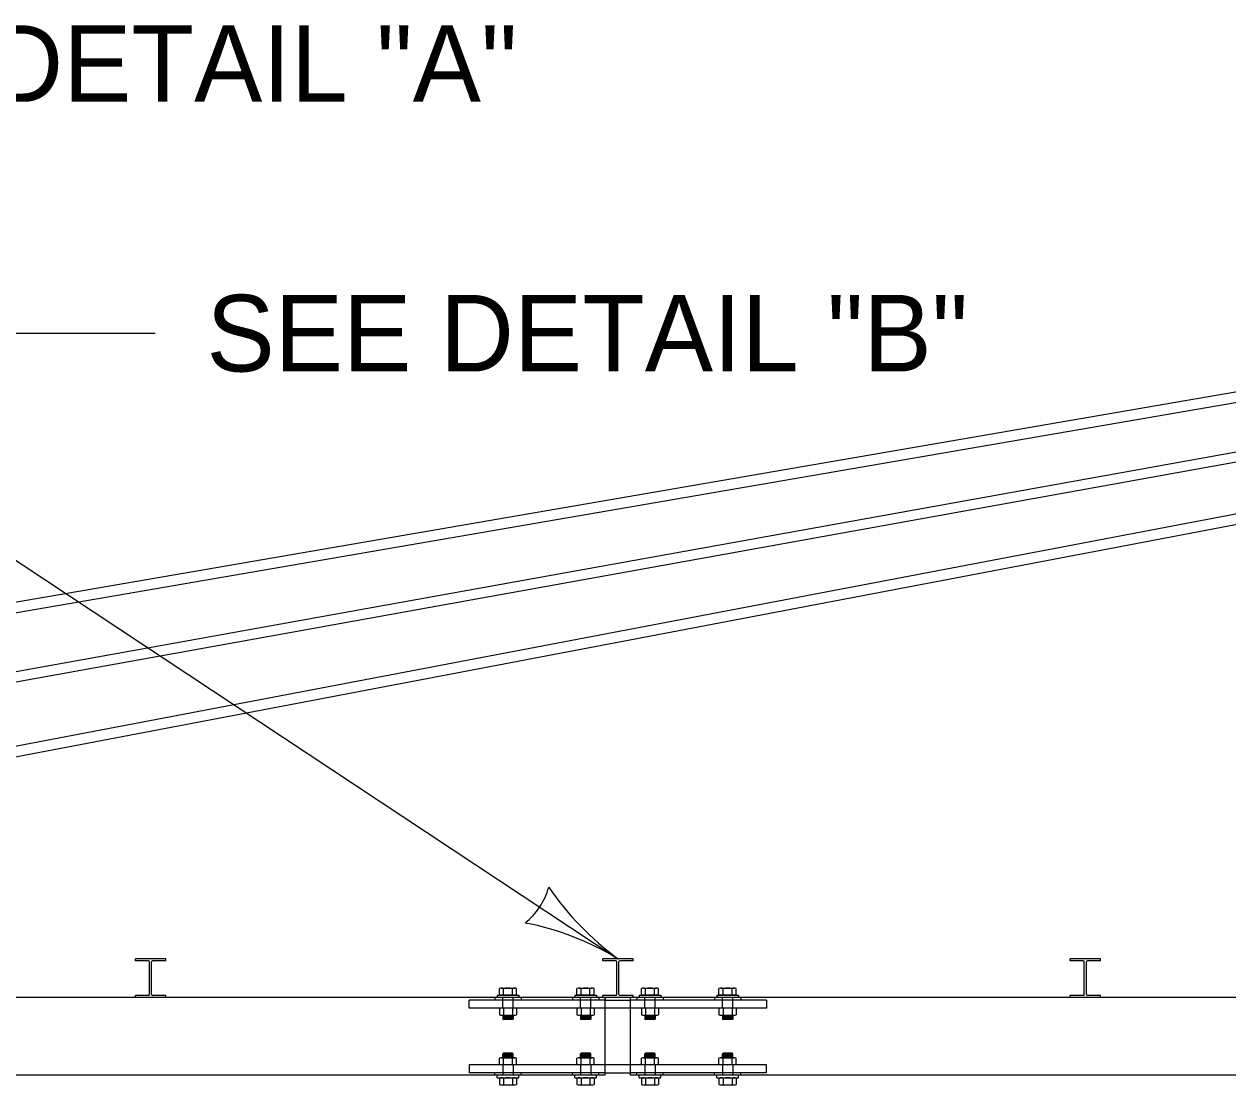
# Model space of a CAD drawing. Extents: x 49991.4 to 50021, y 49987.6 to 50011.4.
# Drawn here: x 50004.377 to 50005.32, y 49996.741 to 49997.572 of the extents above; entities that cross this region are included whole.
import ezdxf

# ---------------------------------------------------------------- set-up
doc = ezdxf.new("R2010")
doc.units = 0
for name, color, linetype in [('Level 1', 7, 'Continuous'), ('Level 2', 7, 'Continuous'), ('Level 3', 7, 'Continuous'), ('Level 4', 7, 'Continuous')]:
    doc.layers.add(name, color=color, linetype=linetype)

msp = doc.modelspace()

# ---------------------------------------------------------------- linework, layer by layer
at = {"layer": 'Level 1'}
for p, q in [((50002.8842, 49996.86275), (50006.12112, 49997.4208)), ((50002.88578, 49996.85474), (50006.12265, 49997.41281)), ((50003.25008, 49996.86273), (50006.12834, 49997.38128)), ((50003.25178, 49996.85474), (50006.1298, 49997.37361)), ((50003.6162, 49996.86274), (50006.13548, 49997.34215)), ((50003.61778, 49996.85474), (50006.137, 49997.33416)), ((50004.48824, 49996.83972), (50004.46456, 49996.83972)), ((50004.46456, 49996.83812), (50004.46456, 49996.83972)), ((50004.4748, 49996.83812), (50004.46456, 49996.83812)), ((50004.4756, 49996.81164), (50004.4756, 49996.83732)), ((50004.4772, 49996.81164), (50004.4772, 49996.83732)), ((50004.48824, 49996.83812), (50004.478, 49996.83812)), ((50004.48824, 49996.83812), (50004.48824, 49996.83972)), ((50004.85424, 49996.83972), (50004.83056, 49996.83972)), ((50004.83056, 49996.83812), (50004.83056, 49996.83972)), ((50004.8408, 49996.83812), (50004.83056, 49996.83812)), ((50004.8416, 49996.81164), (50004.8416, 49996.83732)), ((50004.8432, 49996.81164), (50004.8432, 49996.83732)), ((50004.85424, 49996.83812), (50004.844, 49996.83812)), ((50004.85424, 49996.83812), (50004.85424, 49996.83972)), ((50005.22024, 49996.83972), (50005.19656, 49996.83972)), ((50005.19656, 49996.83812), (50005.19656, 49996.83972)), ((50005.2068, 49996.83812), (50005.19656, 49996.83812)), ((50005.2076, 49996.81164), (50005.2076, 49996.83732)), ((50005.2092, 49996.81164), (50005.2092, 49996.83732)), ((50005.22024, 49996.83812), (50005.21, 49996.83812)), ((50005.22024, 49996.83812), (50005.22024, 49996.83972)), ((50004.74951, 49996.81157), (50004.74951, 49996.81646)), ((50004.7512, 49996.81674), (50004.76134, 49996.81674)), ((50004.75286, 49996.81156), (50004.75286, 49996.81647)), ((50004.7597, 49996.81156), (50004.7597, 49996.81644)), ((50004.76305, 49996.81157), (50004.76305, 49996.81646)), ((50004.81031, 49996.81157), (50004.81031, 49996.81646)), ((50004.812, 49996.81674), (50004.82214, 49996.81674)), ((50004.81366, 49996.81156), (50004.81366, 49996.81647)), ((50004.8205, 49996.81156), (50004.8205, 49996.81644)), ((50004.82385, 49996.81157), (50004.82385, 49996.81646)), ((50004.86071, 49996.81157), (50004.86071, 49996.81646)), ((50004.8624, 49996.81674), (50004.87254, 49996.81674)), ((50004.86406, 49996.81156), (50004.86406, 49996.81647)), ((50004.8709, 49996.81156), (50004.8709, 49996.81644)), ((50004.87425, 49996.81157), (50004.87425, 49996.81646)), ((50004.92151, 49996.81157), (50004.92151, 49996.81646)), ((50004.9232, 49996.81674), (50004.93334, 49996.81674)), ((50004.92486, 49996.81156), (50004.92486, 49996.81647)), ((50004.9317, 49996.81156), (50004.9317, 49996.81646)), ((50004.93505, 49996.81157), (50004.93505, 49996.81646)), ((50004.83228, 49996.80924), (50002.6464, 49996.80924)), ((50004.46456, 49996.80924), (50004.46456, 49996.81084)), ((50004.4748, 49996.81084), (50004.46456, 49996.81084)), ((50004.48824, 49996.81084), (50004.478, 49996.81084)), ((50004.48824, 49996.80924), (50004.48824, 49996.81084)), ((50004.7479, 49996.81124), (50004.76467, 49996.81124)), ((50004.7479, 49996.81124), (50004.7479, 49996.80924)), ((50004.7512, 49996.81129), (50004.76134, 49996.81129)), ((50004.76467, 49996.81124), (50004.76467, 49996.80924)), ((50004.8087, 49996.81124), (50004.82547, 49996.81124)), ((50004.8087, 49996.81124), (50004.8087, 49996.80924)), ((50004.812, 49996.81129), (50004.82214, 49996.81129)), ((50004.82547, 49996.81124), (50004.82547, 49996.80924)), ((50004.83056, 49996.80924), (50004.83056, 49996.81084)), ((50004.8408, 49996.81084), (50004.83056, 49996.81084)), ((50004.85424, 49996.80924), (50004.83056, 49996.80924)), ((50004.83228, 49996.74844), (50004.83228, 49996.80924)), ((50004.83228, 49996.80924), (50004.83228, 49996.80732)), ((50004.83228, 49996.80732), (50004.85228, 49996.80732)), ((50004.85424, 49996.81084), (50004.844, 49996.81084)), ((50004.85228, 49996.74844), (50004.85228, 49996.80924)), ((50007.0284, 49996.80924), (50004.85228, 49996.80924)), ((50004.85424, 49996.80924), (50004.85424, 49996.81084)), ((50004.8591, 49996.81124), (50004.87587, 49996.81124)), ((50004.8591, 49996.81124), (50004.8591, 49996.80924)), ((50004.8624, 49996.81129), (50004.87254, 49996.81129)), ((50004.87587, 49996.81124), (50004.87587, 49996.80924)), ((50004.9199, 49996.81124), (50004.93667, 49996.81124)), ((50004.9199, 49996.81124), (50004.9199, 49996.80924)), ((50004.9232, 49996.81129), (50004.93334, 49996.81129)), ((50004.93667, 49996.81124), (50004.93667, 49996.80924)), ((50005.19656, 49996.80924), (50005.19656, 49996.81084)), ((50005.2068, 49996.81084), (50005.19656, 49996.81084)), ((50005.22024, 49996.81084), (50005.21, 49996.81084)), ((50005.22024, 49996.80924), (50005.22024, 49996.81084)), ((50004.85228, 49996.80096), (50004.83228, 49996.80096)), ((50004.85228, 49996.75672), (50004.83228, 49996.75672)), ((50004.83228, 49996.74844), (50004.83228, 49996.75036)), ((50004.83228, 49996.75036), (50004.85228, 49996.75036)), ((50004.83228, 49996.74844), (50004.1916, 49996.74844)), ((50004.7479, 49996.74645), (50004.7479, 49996.74844)), ((50004.7479, 49996.74645), (50004.76467, 49996.74645)), ((50004.74951, 49996.74612), (50004.74951, 49996.74123)), ((50004.7512, 49996.7464), (50004.76134, 49996.7464)), ((50004.7512, 49996.74095), (50004.76134, 49996.74095)), ((50004.75286, 49996.74613), (50004.75286, 49996.74122)), ((50004.7597, 49996.74613), (50004.7597, 49996.74124)), ((50004.76305, 49996.74612), (50004.76305, 49996.74123)), ((50004.76467, 49996.74645), (50004.76467, 49996.74844)), ((50004.8087, 49996.74645), (50004.8087, 49996.74844)), ((50004.8087, 49996.74645), (50004.82547, 49996.74645)), ((50004.81031, 49996.74612), (50004.81031, 49996.74123)), ((50004.812, 49996.7464), (50004.82214, 49996.7464)), ((50004.812, 49996.74095), (50004.82214, 49996.74095)), ((50004.81366, 49996.74613), (50004.81366, 49996.74122)), ((50004.8205, 49996.74613), (50004.8205, 49996.74124)), ((50004.82385, 49996.74612), (50004.82385, 49996.74123)), ((50004.82547, 49996.74645), (50004.82547, 49996.74844)), ((50007.0284, 49996.74844), (50004.85228, 49996.74844)), ((50004.8591, 49996.74645), (50004.8591, 49996.74844)), ((50004.8591, 49996.74645), (50004.87587, 49996.74645)), ((50004.86071, 49996.74612), (50004.86071, 49996.74123)), ((50004.8624, 49996.7464), (50004.87254, 49996.7464)), ((50004.8624, 49996.74095), (50004.87254, 49996.74095)), ((50004.86406, 49996.74613), (50004.86406, 49996.74122)), ((50004.8709, 49996.74613), (50004.8709, 49996.74124)), ((50004.87425, 49996.74612), (50004.87425, 49996.74123)), ((50004.87587, 49996.74645), (50004.87587, 49996.74844)), ((50004.9199, 49996.74645), (50004.9199, 49996.74844)), ((50004.9199, 49996.74645), (50004.93667, 49996.74645)), ((50004.92151, 49996.74612), (50004.92151, 49996.74123)), ((50004.9232, 49996.7464), (50004.93334, 49996.7464)), ((50004.9232, 49996.74095), (50004.93334, 49996.74095)), ((50004.92486, 49996.74613), (50004.92486, 49996.74122)), ((50004.9317, 49996.74613), (50004.9317, 49996.74124)), ((50004.93505, 49996.74612), (50004.93505, 49996.74123)), ((50004.93667, 49996.74645), (50004.93667, 49996.74844))]:
    msp.add_line(p, q, dxfattribs=at)
for centre, start, end in [((50004.4748, 49996.83732), 0, 90), ((50004.478, 49996.83732), 90, 180), ((50004.8408, 49996.83732), 0, 90), ((50004.844, 49996.83732), 90, 180), ((50005.2068, 49996.83732), 0, 90), ((50005.21, 49996.83732), 90, 180), ((50004.4748, 49996.81164), 270, 0), ((50004.478, 49996.81164), 180, 270), ((50004.8408, 49996.81164), 270, 0), ((50004.844, 49996.81164), 180, 270), ((50005.2068, 49996.81164), 270, 0), ((50005.21, 49996.81164), 180, 270)]:
    msp.add_arc(centre, 0.0008, start, end, dxfattribs=at)
for centre, major_axis, start_param, end_param in [((50004.7512, 49996.81463), (0.00339, 0), 1.056847, 2.094396), ((50004.75628, 49996.80829), (0.01355, 0), 1.315951, 1.825641), ((50004.76136, 49996.81463), (0.00339, 0), 1.047198, 2.084746), ((50004.812, 49996.81463), (0.00339, 0), 1.056847, 2.094396), ((50004.81708, 49996.80829), (0.01355, 0), 1.315951, 1.825641), ((50004.82216, 49996.81463), (0.00339, 0), 1.047198, 2.084746), ((50004.8624, 49996.81463), (0.00339, 0), 1.056847, 2.094396), ((50004.86748, 49996.80829), (0.01355, 0), 1.315951, 1.825641), ((50004.87256, 49996.81463), (0.00339, 0), 1.047198, 2.084746), ((50004.9232, 49996.81463), (0.00339, 0), 1.056847, 2.094396), ((50004.92828, 49996.80829), (0.01355, 0), 1.315951, 1.825641), ((50004.93336, 49996.81463), (0.00339, 0), 1.047198, 2.084746), ((50004.7512, 49996.8134), (0.00339, 0), 4.188789, 5.226338), ((50004.75628, 49996.81974), (0.01355, 0), 4.457545, 4.967235), ((50004.76136, 49996.8134), (0.00339, 0), 4.198439, 5.235988), ((50004.812, 49996.8134), (0.00339, 0), 4.188789, 5.226338), ((50004.81708, 49996.81974), (0.01355, 0), 4.457545, 4.967235), ((50004.82216, 49996.8134), (0.00339, 0), 4.198439, 5.235988), ((50004.8624, 49996.8134), (0.00339, 0), 4.188789, 5.226338), ((50004.86748, 49996.81974), (0.01355, 0), 4.457545, 4.967235), ((50004.87256, 49996.8134), (0.00339, 0), 4.198439, 5.235988), ((50004.9232, 49996.8134), (0.00339, 0), 4.188789, 5.226338), ((50004.92828, 49996.81974), (0.01355, 0), 4.457545, 4.967235), ((50004.93336, 49996.8134), (0.00339, 0), 4.198439, 5.235988), ((50004.7512, 49996.74429), (0.00339, 0), 1.056847, 2.094396), ((50004.7512, 49996.74306), (0.00339, 0), 4.188789, 5.226338), ((50004.75628, 49996.73795), (0.01355, 0), 1.31595, 1.825641), ((50004.75628, 49996.7494), (0.01355, 0), 4.457545, 4.967234), ((50004.76136, 49996.74429), (0.00339, 0), 1.047198, 2.084746), ((50004.76136, 49996.74306), (0.00339, 0), 4.198439, 5.235988), ((50004.812, 49996.74429), (0.00339, 0), 1.056847, 2.094396), ((50004.812, 49996.74306), (0.00339, 0), 4.188789, 5.226338), ((50004.81708, 49996.73795), (0.01355, 0), 1.31595, 1.825641), ((50004.81708, 49996.7494), (0.01355, 0), 4.457545, 4.967234), ((50004.82216, 49996.74429), (0.00339, 0), 1.047198, 2.084746), ((50004.82216, 49996.74306), (0.00339, 0), 4.198439, 5.235988), ((50004.8624, 49996.74429), (0.00339, 0), 1.056847, 2.094396), ((50004.8624, 49996.74306), (0.00339, 0), 4.188789, 5.226338), ((50004.86748, 49996.73795), (0.01355, 0), 1.31595, 1.825641), ((50004.86748, 49996.7494), (0.01355, 0), 4.457545, 4.967234), ((50004.87256, 49996.74429), (0.00339, 0), 1.047198, 2.084746), ((50004.87256, 49996.74306), (0.00339, 0), 4.198439, 5.235988), ((50004.9232, 49996.74429), (0.00339, 0), 1.056847, 2.094396), ((50004.9232, 49996.74306), (0.00339, 0), 4.188789, 5.226338), ((50004.92828, 49996.73795), (0.01355, 0), 1.31595, 1.825641), ((50004.92828, 49996.7494), (0.01355, 0), 4.457545, 4.967234), ((50004.93336, 49996.74429), (0.00339, 0), 1.047198, 2.084746), ((50004.93336, 49996.74306), (0.00339, 0), 4.198439, 5.235988)]:
    msp.add_ellipse(centre, major_axis=major_axis, ratio=0.623816, start_param=start_param, end_param=end_param, dxfattribs=at)
at = {"layer": 'Level 3'}
for p, q in [((50004.34941, 49997.32964), (50004.48011, 49997.32964)), ((50004.31385, 49997.18926), (50004.8424, 49996.83972))]:
    msp.add_line(p, q, dxfattribs=at)
for centre, radius, start, end in [((50004.73546, 49996.91044), 0.05477, 308.66104, 344.3834), ((50004.98035, 49997.02748), 0.233, 214.44506, 233.69491), ((50004.72751, 49996.64939), 0.22232, 58.8827, 79.06621)]:
    msp.add_arc(centre, radius, start, end, dxfattribs=at)
at = {"layer": 'Level 4'}
for p, q in [((50004.72588, 49996.80096), (50004.72588, 49996.80732)), ((50004.83228, 49996.80732), (50004.72588, 49996.80732)), ((50004.7459, 49996.80924), (50004.7459, 49996.80732)), ((50004.75228, 49996.80096), (50004.75228, 49996.80924)), ((50004.76028, 49996.80096), (50004.76028, 49996.80924)), ((50004.76667, 49996.80924), (50004.76667, 49996.80732)), ((50004.8067, 49996.80924), (50004.8067, 49996.80732)), ((50004.81309, 49996.80096), (50004.81309, 49996.80924)), ((50004.82109, 49996.80096), (50004.82109, 49996.80924)), ((50004.82747, 49996.80924), (50004.82747, 49996.80732)), ((50004.95868, 49996.80732), (50004.85228, 49996.80732)), ((50004.8571, 49996.80924), (50004.8571, 49996.80732)), ((50004.86348, 49996.80096), (50004.86348, 49996.80924)), ((50004.87148, 49996.80096), (50004.87148, 49996.80924)), ((50004.87787, 49996.80924), (50004.87787, 49996.80732)), ((50004.9179, 49996.80924), (50004.9179, 49996.80732)), ((50004.92429, 49996.80096), (50004.92429, 49996.80924)), ((50004.93229, 49996.80096), (50004.93229, 49996.80924)), ((50004.93867, 49996.80924), (50004.93867, 49996.80732)), ((50004.95868, 49996.80732), (50004.95868, 49996.80096)), ((50004.83228, 49996.80096), (50004.72588, 49996.80096)), ((50004.74951, 49996.80068), (50004.74951, 49996.79579)), ((50004.75286, 49996.80069), (50004.75286, 49996.79579)), ((50004.75971, 49996.80069), (50004.75971, 49996.79578)), ((50004.76306, 49996.80068), (50004.76306, 49996.79579)), ((50004.81031, 49996.80068), (50004.81031, 49996.79579)), ((50004.81366, 49996.80069), (50004.81366, 49996.79579)), ((50004.82051, 49996.80069), (50004.82051, 49996.79578)), ((50004.82386, 49996.80068), (50004.82386, 49996.79579)), ((50004.95868, 49996.80096), (50004.85228, 49996.80096)), ((50004.86071, 49996.80068), (50004.86071, 49996.79579)), ((50004.86406, 49996.80069), (50004.86406, 49996.79579)), ((50004.87091, 49996.80069), (50004.87091, 49996.79578)), ((50004.87426, 49996.80068), (50004.87426, 49996.79579)), ((50004.92151, 49996.80068), (50004.92151, 49996.79579)), ((50004.92486, 49996.80069), (50004.92486, 49996.79578)), ((50004.93171, 49996.80069), (50004.93171, 49996.79578)), ((50004.93506, 49996.80068), (50004.93506, 49996.79579)), ((50004.75121, 49996.79551), (50004.76135, 49996.79551)), ((50004.75228, 49996.79551), (50004.75228, 49996.79244)), ((50004.75228, 49996.79244), (50004.75268, 49996.79204)), ((50004.75988, 49996.79524), (50004.75268, 49996.79524)), ((50004.75988, 49996.79444), (50004.75268, 49996.79444)), ((50004.75988, 49996.79364), (50004.75268, 49996.79364)), ((50004.75988, 49996.79284), (50004.75268, 49996.79284)), ((50004.75988, 49996.79204), (50004.75268, 49996.79204)), ((50004.76028, 49996.79244), (50004.75988, 49996.79204)), ((50004.76028, 49996.79551), (50004.76028, 49996.79244)), ((50004.81201, 49996.79551), (50004.82215, 49996.79551)), ((50004.81309, 49996.79551), (50004.81309, 49996.79244)), ((50004.81309, 49996.79244), (50004.81349, 49996.79204)), ((50004.82069, 49996.79524), (50004.81349, 49996.79524)), ((50004.82069, 49996.79444), (50004.81349, 49996.79444)), ((50004.82069, 49996.79364), (50004.81349, 49996.79364)), ((50004.82069, 49996.79284), (50004.81349, 49996.79284)), ((50004.82069, 49996.79204), (50004.81349, 49996.79204)), ((50004.82109, 49996.79244), (50004.82069, 49996.79204)), ((50004.82109, 49996.79551), (50004.82109, 49996.79244)), ((50004.86241, 49996.79551), (50004.87255, 49996.79551)), ((50004.86349, 49996.79551), (50004.86349, 49996.79244)), ((50004.86349, 49996.79244), (50004.86389, 49996.79204)), ((50004.87109, 49996.79524), (50004.86389, 49996.79524)), ((50004.87109, 49996.79444), (50004.86389, 49996.79444)), ((50004.87109, 49996.79364), (50004.86389, 49996.79364)), ((50004.87109, 49996.79284), (50004.86389, 49996.79284)), ((50004.87109, 49996.79204), (50004.86389, 49996.79204)), ((50004.87149, 49996.79244), (50004.87109, 49996.79204)), ((50004.87149, 49996.79551), (50004.87149, 49996.79244)), ((50004.92321, 49996.79551), (50004.93335, 49996.79551)), ((50004.92429, 49996.79551), (50004.92429, 49996.79244)), ((50004.92429, 49996.79244), (50004.92469, 49996.79204)), ((50004.93189, 49996.79524), (50004.92469, 49996.79524)), ((50004.93189, 49996.79444), (50004.92469, 49996.79444)), ((50004.93189, 49996.79364), (50004.92469, 49996.79364)), ((50004.93189, 49996.79284), (50004.92469, 49996.79284)), ((50004.93189, 49996.79204), (50004.92469, 49996.79204)), ((50004.93229, 49996.79244), (50004.93189, 49996.79204)), ((50004.93229, 49996.79551), (50004.93229, 49996.79244)), ((50004.74951, 49996.75701), (50004.74951, 49996.76189)), ((50004.75121, 49996.76218), (50004.76135, 49996.76218)), ((50004.75228, 49996.76525), (50004.75268, 49996.76565)), ((50004.75228, 49996.76218), (50004.75228, 49996.76525)), ((50004.75988, 49996.76565), (50004.75268, 49996.76565)), ((50004.75988, 49996.76485), (50004.75268, 49996.76485)), ((50004.75988, 49996.76405), (50004.75268, 49996.76405)), ((50004.75988, 49996.76325), (50004.75268, 49996.76325)), ((50004.75988, 49996.76245), (50004.75268, 49996.76245)), ((50004.75286, 49996.757), (50004.75286, 49996.7619)), ((50004.75971, 49996.757), (50004.75971, 49996.7619)), ((50004.76028, 49996.76525), (50004.75988, 49996.76565)), ((50004.76028, 49996.76218), (50004.76028, 49996.76525)), ((50004.76306, 49996.75701), (50004.76306, 49996.76189)), ((50004.81031, 49996.75701), (50004.81031, 49996.76189)), ((50004.81201, 49996.76218), (50004.82215, 49996.76218)), ((50004.81309, 49996.76525), (50004.81349, 49996.76565)), ((50004.81309, 49996.76218), (50004.81309, 49996.76525)), ((50004.82069, 49996.76565), (50004.81349, 49996.76565)), ((50004.82069, 49996.76485), (50004.81349, 49996.76485)), ((50004.82069, 49996.76405), (50004.81349, 49996.76405)), ((50004.82069, 49996.76325), (50004.81349, 49996.76325)), ((50004.82069, 49996.76245), (50004.81349, 49996.76245)), ((50004.81366, 49996.757), (50004.81366, 49996.7619)), ((50004.82051, 49996.757), (50004.82051, 49996.7619)), ((50004.82109, 49996.76525), (50004.82069, 49996.76565)), ((50004.82109, 49996.76218), (50004.82109, 49996.76525)), ((50004.82386, 49996.75701), (50004.82386, 49996.76189)), ((50004.86071, 49996.75701), (50004.86071, 49996.76189)), ((50004.86241, 49996.76218), (50004.87255, 49996.76218)), ((50004.86349, 49996.76525), (50004.86389, 49996.76565)), ((50004.86349, 49996.76218), (50004.86349, 49996.76525)), ((50004.87109, 49996.76565), (50004.86389, 49996.76565)), ((50004.87109, 49996.76485), (50004.86389, 49996.76485)), ((50004.87109, 49996.76405), (50004.86389, 49996.76405)), ((50004.87109, 49996.76325), (50004.86389, 49996.76325)), ((50004.87109, 49996.76245), (50004.86389, 49996.76245)), ((50004.86406, 49996.757), (50004.86406, 49996.7619)), ((50004.87091, 49996.757), (50004.87091, 49996.7619)), ((50004.87149, 49996.76525), (50004.87109, 49996.76565)), ((50004.87149, 49996.76218), (50004.87149, 49996.76525)), ((50004.87426, 49996.75701), (50004.87426, 49996.76189)), ((50004.92151, 49996.75701), (50004.92151, 49996.76189)), ((50004.92321, 49996.76218), (50004.93335, 49996.76218)), ((50004.92429, 49996.76525), (50004.92469, 49996.76565)), ((50004.92429, 49996.76218), (50004.92429, 49996.76525)), ((50004.93189, 49996.76565), (50004.92469, 49996.76565)), ((50004.93189, 49996.76485), (50004.92469, 49996.76485)), ((50004.93189, 49996.76405), (50004.92469, 49996.76405)), ((50004.93189, 49996.76325), (50004.92469, 49996.76325)), ((50004.93189, 49996.76245), (50004.92469, 49996.76245)), ((50004.92486, 49996.757), (50004.92486, 49996.7619)), ((50004.93171, 49996.757), (50004.93171, 49996.7619)), ((50004.93229, 49996.76525), (50004.93189, 49996.76565)), ((50004.93229, 49996.76218), (50004.93229, 49996.76525)), ((50004.93506, 49996.75701), (50004.93506, 49996.76189)), ((50004.72588, 49996.75672), (50004.72588, 49996.75036)), ((50004.83228, 49996.75672), (50004.72588, 49996.75672)), ((50004.83228, 49996.75036), (50004.72588, 49996.75036)), ((50004.7459, 49996.74844), (50004.7459, 49996.75036)), ((50004.75228, 49996.75672), (50004.75228, 49996.74844)), ((50004.76028, 49996.75672), (50004.76028, 49996.74844)), ((50004.76667, 49996.74844), (50004.76667, 49996.75036)), ((50004.8067, 49996.74844), (50004.8067, 49996.75036)), ((50004.81309, 49996.75672), (50004.81309, 49996.74844)), ((50004.82109, 49996.75672), (50004.82109, 49996.74844)), ((50004.82747, 49996.74844), (50004.82747, 49996.75036)), ((50004.95868, 49996.75672), (50004.85228, 49996.75672)), ((50004.95868, 49996.75036), (50004.85228, 49996.75036)), ((50004.8571, 49996.74844), (50004.8571, 49996.75036)), ((50004.86348, 49996.75672), (50004.86348, 49996.74844)), ((50004.87148, 49996.75672), (50004.87148, 49996.74844)), ((50004.87787, 49996.74844), (50004.87787, 49996.75036)), ((50004.9179, 49996.74844), (50004.9179, 49996.75036)), ((50004.92429, 49996.75672), (50004.92429, 49996.74844)), ((50004.93229, 49996.75672), (50004.93229, 49996.74844)), ((50004.93867, 49996.74844), (50004.93867, 49996.75036)), ((50004.95868, 49996.75036), (50004.95868, 49996.75672))]:
    msp.add_line(p, q, dxfattribs=at)
for centre, major_axis, start_param, end_param in [((50004.75121, 49996.79885), (0.00339, 0), 1.056847, 2.094396), ((50004.75629, 49996.79251), (0.01355, 0), 1.31595, 1.825641), ((50004.76137, 49996.79885), (0.00339, 0), 1.047198, 2.084746), ((50004.81201, 49996.79885), (0.00339, 0), 1.056847, 2.094396), ((50004.81709, 49996.79251), (0.01355, 0), 1.31595, 1.825641), ((50004.82217, 49996.79885), (0.00339, 0), 1.047198, 2.084746), ((50004.86241, 49996.79885), (0.00339, 0), 1.056847, 2.094396), ((50004.86749, 49996.79251), (0.01355, 0), 1.31595, 1.825641), ((50004.87257, 49996.79885), (0.00339, 0), 1.047198, 2.084746), ((50004.92321, 49996.79885), (0.00339, 0), 1.056847, 2.094396), ((50004.92829, 49996.79251), (0.01355, 0), 1.31595, 1.825641), ((50004.93337, 49996.79885), (0.00339, 0), 1.047198, 2.084746), ((50004.75121, 49996.79762), (0.00339, 0), 4.188789, 5.226338), ((50004.75629, 49996.80396), (0.01355, 0), 4.457545, 4.967234), ((50004.76137, 49996.79762), (0.00339, 0), 4.198439, 5.235988), ((50004.81201, 49996.79762), (0.00339, 0), 4.188789, 5.226338), ((50004.81709, 49996.80396), (0.01355, 0), 4.457545, 4.967234), ((50004.82217, 49996.79762), (0.00339, 0), 4.198439, 5.235988), ((50004.86241, 49996.79762), (0.00339, 0), 4.188789, 5.226338), ((50004.86749, 49996.80396), (0.01355, 0), 4.457545, 4.967234), ((50004.87257, 49996.79762), (0.00339, 0), 4.198439, 5.235988), ((50004.92321, 49996.79762), (0.00339, 0), 4.188789, 5.226338), ((50004.92829, 49996.80396), (0.01355, 0), 4.457545, 4.967234), ((50004.93337, 49996.79762), (0.00339, 0), 4.198439, 5.235988), ((50004.75121, 49996.76006), (0.00339, 0), 1.056847, 2.094396), ((50004.75629, 49996.75373), (0.01355, 0), 1.315951, 1.825641), ((50004.76137, 49996.76006), (0.00339, 0), 1.047198, 2.084746), ((50004.81201, 49996.76006), (0.00339, 0), 1.056847, 2.094396), ((50004.81709, 49996.75373), (0.01355, 0), 1.315951, 1.825641), ((50004.82217, 49996.76006), (0.00339, 0), 1.047198, 2.084746), ((50004.86241, 49996.76006), (0.00339, 0), 1.056847, 2.094396), ((50004.86749, 49996.75373), (0.01355, 0), 1.315951, 1.825641), ((50004.87257, 49996.76006), (0.00339, 0), 1.047198, 2.084746), ((50004.92321, 49996.76006), (0.00339, 0), 1.056847, 2.094396), ((50004.92829, 49996.75373), (0.01355, 0), 1.315951, 1.825641), ((50004.93337, 49996.76006), (0.00339, 0), 1.047198, 2.084746), ((50004.75121, 49996.75884), (0.00339, 0), 4.188789, 5.226338), ((50004.75629, 49996.76517), (0.01355, 0), 4.457545, 4.967235), ((50004.76137, 49996.75884), (0.00339, 0), 4.198439, 5.235988), ((50004.81201, 49996.75884), (0.00339, 0), 4.188789, 5.226338), ((50004.81709, 49996.76517), (0.01355, 0), 4.457545, 4.967235), ((50004.82217, 49996.75884), (0.00339, 0), 4.198439, 5.235988), ((50004.86241, 49996.75884), (0.00339, 0), 4.188789, 5.226338), ((50004.86749, 49996.76517), (0.01355, 0), 4.457545, 4.967235), ((50004.87257, 49996.75884), (0.00339, 0), 4.198439, 5.235988), ((50004.92321, 49996.75884), (0.00339, 0), 4.188789, 5.226338), ((50004.92829, 49996.76517), (0.01355, 0), 4.457545, 4.967235), ((50004.93337, 49996.75884), (0.00339, 0), 4.198439, 5.235988)]:
    msp.add_ellipse(centre, major_axis=major_axis, ratio=0.623816, start_param=start_param, end_param=end_param, dxfattribs=at)

# ---------------------------------------------------------------- texts
at = {"layer": 'Level 2'}
for s, p in [('SEE DETAIL "A"', (50004.16713, 49997.51082)), ('SEE DETAIL "B"', (50004.52011, 49997.29964))]:
    msp.add_text(s, height=0.06, dxfattribs=at).set_placement(p)

doc.saveas('drawing.dxf')
